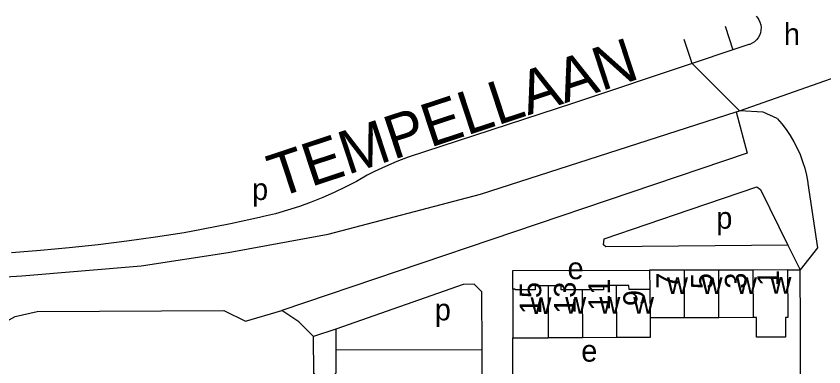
# Model space of a CAD drawing. Extents: x 159675 to 162108, y 386471 to 388472.
# Drawn here: x 161699.1 to 161848.2, y 388325.9 to 388390.6 of the extents above; entities that cross this region are included whole.
import ezdxf

# ---------------------------------------------------------------- set-up
doc = ezdxf.new("R2010")
doc.units = 0
for name, color, linetype in [('BLT_Basislijn', 7, 'Continuous'), ('BLT_Bebouwing', 7, 'Continuous'), ('BLT_Centroide', 7, 'Continuous'), ('BLT_Huisnummer', 7, 'Continuous'), ('BLT_Huisnummer_ tussenligend', 7, 'Continuous'), ('BLT_Onderverdeling_panden', 7, 'Continuous'), ('BLT_Straatnaam_hoofdweg', 7, 'Continuous'), ('BLT_Vlakafsluiter', 7, 'Continuous')]:
    doc.layers.add(name, color=color, linetype=linetype)

msp = doc.modelspace()

# ---------------------------------------------------------------- linework, layer by layer
at = {"layer": 'BLT_Basislijn'}
for p, q in [((161830.01, 388388.75), (161831.41, 388384.36)), ((161841.59, 388348.37), (161843.85, 388343.78)), ((161841.53, 388343.78), (161843.85, 388343.78)), ((161758.08, 388332.85), (161753.96, 388331.47)), ((161758.08, 388332.85), (161758.11, 388328.97)), ((161790.8, 388319.12), (161790.8, 388331.24)), ((161785.14, 388329.03), (161758.11, 388328.97))]:
    msp.add_line(p, q, dxfattribs=at)
for points in [[(161835.71, 388390.6), (161836.01, 388390.21), (161836.19, 388389.93), (161836.4, 388389.48), (161836.55, 388389), (161836.61, 388388.51), (161836.6, 388388.01), (161836.5, 388387.52), (161836.33, 388387.05), (161836.09, 388386.61), (161835.77, 388386.22), (161835.4, 388385.88), (161834.99, 388385.61), (161834.53, 388385.4), (161834.38, 388385.35), (161831.41, 388384.36)], [(161823.88, 388381.85), (161822.39, 388386.27)], [(161831.41, 388384.36), (161823.88, 388381.85)], [(161823.88, 388381.85), (161801.98, 388374.55), (161771.43, 388364.57), (161769.33, 388363.76), (161767.25, 388362.88), (161765.21, 388361.93), (161763.88, 388361.26), (161761.88, 388360.11), (161759.84, 388359.04), (161757.77, 388358.05), (161755.66, 388357.12), (161753.52, 388356.27), (161751.35, 388355.49), (161749.16, 388354.78), (161746.94, 388354.16), (161744.7, 388353.61), (161743.98, 388353.45), (161738.63, 388352.3), (161733.26, 388351.22), (161730.07, 388350.62), (161724.78, 388349.81), (161719.48, 388349.08), (161714.17, 388348.42), (161708.85, 388347.85), (161703.52, 388347.35), (161698.19, 388346.94)], [(161311.49, 388339.16), (161655.24, 388340.99), (161682.93, 388341.62), (161700.12, 388342.7), (161722.11, 388344.51), (161738.22, 388346.98), (161756.66, 388350.37), (161784.83, 388357.74), (161832.04, 388372.93)], [(161832.04, 388372.93), (161834.03, 388365.3), (161748.13, 388336.28)], [(161832.04, 388372.93), (161832.65, 388373.15)], [(161839.57, 388371.74), (161837.02, 388372.86), (161832.65, 388373.15)], [(161839.57, 388371.74), (161840.45, 388370.74), (161841.26, 388369.68), (161842.01, 388368.59), (161842.69, 388367.44), (161843.3, 388366.26), (161843.84, 388365.05), (161844.3, 388363.8), (161844.69, 388362.53), (161845, 388361.24), (161845.23, 388359.93), (161845.27, 388359.71)], [(161823.52, 388354.94), (161835.82, 388359.11), (161836.54, 388358.65), (161841.59, 388348.37)], [(161845.27, 388359.71), (161847.03, 388347.83), (161843.85, 388343.78)], [(161841.59, 388348.37), (161807.93, 388348.07), (161807.5, 388348.43), (161807.66, 388349.55), (161823.52, 388354.94)], [(161790.78, 388340.25), (161790.75, 388343.66), (161816.04, 388343.71)], [(161843.88, 388322.6), (161843.91, 388334.47), (161843.86, 388342.9), (161843.85, 388343.78)], [(161785.14, 388329.03), (161785.06, 388339.74), (161783.65, 388341.14), (161781.59, 388341.1), (161758.08, 388332.85)], [(161693.96, 388332.48), (161698.84, 388335.19), (161702.94, 388336.14), (161737.41, 388336.28), (161741.39, 388334.35), (161748.13, 388336.28)], [(161753.96, 388331.47), (161751.28, 388334.2), (161748.13, 388336.28)], [(161758.11, 388328.97), (161758.09, 388324.76), (161756.92, 388323.51), (161755.39, 388323.48), (161754.05, 388324.69), (161753.96, 388331.47)], [(161754.34, 388307.52), (161754.32, 388315.18), (161755.45, 388317.07), (161756.66, 388317.37), (161757.62, 388316.89), (161758.57, 388315.84), (161759.02, 388313.27), (161784.87, 388313.17), (161785.15, 388313.57), (161785.14, 388329.03)]]:
    msp.add_lwpolyline(points, dxfattribs=at)
at = {"layer": 'BLT_Bebouwing'}
for p, q in [((161822.45, 388343.72), (161816.04, 388343.71)), ((161816.04, 388343.71), (161816.05, 388340.18)), ((161828.81, 388343.74), (161822.45, 388343.72)), ((161835.17, 388343.76), (161828.81, 388343.74)), ((161841.53, 388343.78), (161835.17, 388343.76)), ((161790.78, 388340.25), (161790.8, 388331.24)), ((161828.84, 388334.96), (161822.47, 388334.94)), ((161835.2, 388334.98), (161828.84, 388334.96)), ((161822.47, 388334.94), (161816.11, 388334.93)), ((161803.62, 388331.28), (161797.32, 388331.26)), ((161809.9, 388331.29), (161803.62, 388331.28))]:
    msp.add_line(p, q, dxfattribs=at)
for points in [[(161841.53, 388343.78), (161841.56, 388335), (161841.12, 388335), (161841.13, 388331.39), (161835.79, 388331.38), (161835.78, 388334.98), (161835.2, 388334.98)], [(161809.87, 388340.93), (161807.5, 388340.93), (161807.51, 388340.12), (161803.59, 388340.11)], [(161816.05, 388340.18), (161812.24, 388340.17), (161812.23, 388340.94), (161809.87, 388340.93)], [(161797.29, 388340.85), (161794.9, 388340.85), (161794.9, 388340.1), (161791.22, 388340.09), (161791.22, 388340.25), (161790.78, 388340.25)], [(161803.59, 388340.11), (161799.68, 388340.1), (161799.68, 388340.86), (161797.29, 388340.85)], [(161816.11, 388334.93), (161816.12, 388331.31), (161809.9, 388331.29)], [(161790.8, 388331.24), (161795.8, 388331.25), (161797.32, 388331.26)]]:
    msp.add_lwpolyline(points, dxfattribs=at)
at = {"layer": 'BLT_Onderverdeling_panden'}
for p, q in [((161822.47, 388334.94), (161822.45, 388343.72)), ((161828.84, 388334.96), (161828.81, 388343.74)), ((161835.2, 388334.98), (161835.17, 388343.76)), ((161809.87, 388340.93), (161809.9, 388331.29)), ((161797.29, 388340.85), (161797.32, 388331.26)), ((161803.59, 388340.11), (161803.62, 388331.28)), ((161816.05, 388340.18), (161816.11, 388334.93))]:
    msp.add_line(p, q, dxfattribs=at)
at = {"layer": 'BLT_Vlakafsluiter'}
for points in [[(161832.65, 388373.15), (161865.23, 388384.59)], [(161832.65, 388373.15), (161823.88, 388381.85)]]:
    msp.add_lwpolyline(points, dxfattribs=at)

# ---------------------------------------------------------------- texts
at = {"layer": 'BLT_Centroide'}
for s, p in [('h', (161840.83, 388385.29)), ('p', (161742.62, 388356.68)), ('p', (161828.35, 388351.39)), ('e', (161800.88, 388342.09)), ('w', (161832, 388339.36)), ('w', (161838.36, 388339.39)), ('w', (161819.25, 388339.33)), ('w', (161825.64, 388339.33)), ('w', (161794.05, 388335.67)), ('w', (161800.45, 388335.69)), ('w', (161806.75, 388335.7)), ('w', (161813, 388335.73)), ('p', (161776.36, 388334.47)), ('e', (161803.41, 388326.86))]:
    msp.add_text(s, height=4, dxfattribs=at).set_placement(p)
at = {"layer": 'BLT_Huisnummer'}
for s, p in [('5', (161827.7, 388340.22)), ('1', (161839.9, 388340.79)), ('15', (161796.01, 388335.6)), ('9', (161815.18, 388337.1))]:
    msp.add_text(s, height=4, rotation=89.8369, dxfattribs=at).set_placement(p)
at = {"layer": 'BLT_Huisnummer_ tussenligend'}
for s, p in [('7', (161821.27, 388340.31)), ('3', (161833.95, 388340.32)), ('13', (161802.4, 388335.68)), ('11', (161808.73, 388336.26))]:
    msp.add_text(s, height=4, rotation=90.1631, dxfattribs=at).set_placement(p)
at = {"layer": 'BLT_Straatnaam_hoofdweg'}
msp.add_text('TEMPELLAAN', height=8, rotation=18.2391, dxfattribs=at).set_placement((161747.26, 388357.02))

doc.saveas('drawing.dxf')
